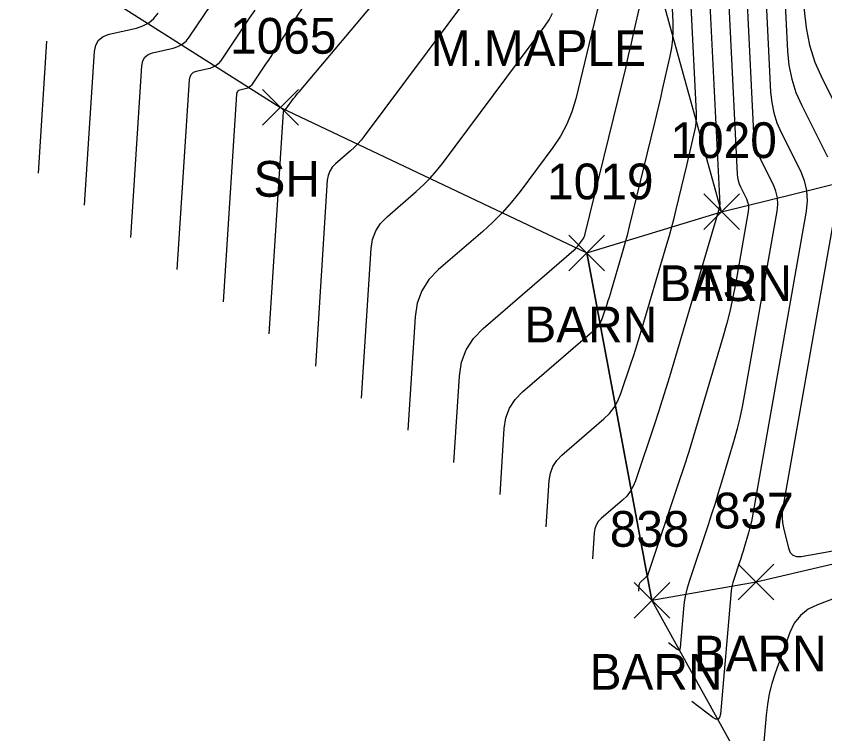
# Model space of a CAD drawing. Extents: x 1650836 to 1652450, y 332578 to 333908.
# Drawn here: x 1651941.6 to 1651986.84, y 332758.18 to 332798.32 of the extents above; entities that cross this region are included whole.
import ezdxf

# ---------------------------------------------------------------- set-up
doc = ezdxf.new("R2010")
doc.units = 0
for name, color, linetype in [('L_A', 7, 'Continuous'), ('L_C', 7, 'Continuous'), ('L_I', 7, 'Continuous'), ('L_TIC', 7, 'Continuous'), ('LBC', 7, 'Continuous'), ('LELB', 7, 'Continuous'), ('LSOGCMA', 7, 'Continuous'), ('LSOGCMI', 7, 'Continuous'), ('LSOGP', 7, 'Continuous')]:
    doc.layers.add(name, color=color, linetype=linetype)

msp = doc.modelspace()

# ---------------------------------------------------------------- linework, layer by layer
at = {"layer": 'L_TIC'}
for points in [[(1651955.389, 332792.224), (1651957.389, 332794.224)], [(1651957.389, 332792.224), (1651955.389, 332794.224)], [(1651980.067, 332786.388), (1651982.067, 332788.388)], [(1651982.067, 332786.388), (1651980.067, 332788.388)], [(1651980.067, 332786.388), (1651982.067, 332788.388)], [(1651982.067, 332786.388), (1651980.067, 332788.388)], [(1651972.519, 332784.08), (1651974.519, 332786.08)], [(1651974.519, 332784.08), (1651972.519, 332786.08)], [(1651981.996, 332765.671), (1651983.996, 332767.671)], [(1651983.996, 332765.671), (1651981.996, 332767.671)], [(1651976.172, 332764.646), (1651978.172, 332766.646)], [(1651978.172, 332764.646), (1651976.172, 332766.646)]]:
    msp.add_lwpolyline(points, dxfattribs=at)
at = {"layer": 'LBC'}
msp.add_lwpolyline([(1652023.947, 332796.746), (1652025.548, 332786.282), (1652005.235, 332781.934), (1652007.106, 332772.495), (1652006.921, 332772.261), (1651982.996, 332766.671), (1651977.172, 332765.646), (1651973.519, 332785.08), (1651981.067, 332787.388), (1651992.104, 332790.093), (1652005.024, 332792.832)], dxfattribs=at)
at = {"layer": 'LELB'}
msp.add_lwpolyline([(1651981.067, 332787.388), (1651974.596, 332810.786), (1651972.976, 332830.46), (1651956.891, 332837.411), (1651913.583, 332855.638), (1651885.106, 332867.214), (1651834.429, 332888.588)], dxfattribs=at)
at = {"layer": 'LSOGCMA'}
msp.add_lwpolyline([(1651966.091, 332773.361), (1651966.4, 332778.193), (1651966.521, 332778.963), (1651966.783, 332779.664), (1651967.184, 332780.296), (1651967.725, 332780.857), (1651972.798, 332785.23), (1651972.868, 332785.294), (1651972.935, 332785.362), (1651972.997, 332785.433), (1651973.056, 332785.507), (1651973.284, 332785.813), (1651973.337, 332785.891), (1651973.381, 332785.974), (1651973.416, 332786.06), (1651973.443, 332786.151), (1651975.535, 332794.734), (1651975.702, 332795.424), (1651975.866, 332796.115), (1651976.026, 332796.806), (1651976.184, 332797.498), (1651976.809, 332800.267)], dxfattribs=at)
at = {"layer": 'LSOGCMI'}
for points in [[(1651986.916, 332818.732), (1651986.557, 332816.279), (1651986.495, 332815.844), (1651986.434, 332815.409), (1651986.375, 332814.974), (1651986.319, 332814.538), (1651985.584, 332808.772), (1651985.468, 332807.665), (1651985.4, 332806.556), (1651985.382, 332805.444), (1651985.412, 332804.332), (1651985.691, 332798.664), (1651985.791, 332797.669), (1651985.991, 332796.701), (1651986.291, 332795.759), (1651986.691, 332794.844), (1651988.494, 332791.234)], [(1651968.674, 332771.563), (1651968.911, 332775.268), (1651969.004, 332775.859), (1651969.204, 332776.397), (1651969.512, 332776.881), (1651969.927, 332777.312), (1651973.966, 332780.794), (1651974.109, 332780.934), (1651974.23, 332781.09), (1651974.328, 332781.261), (1651974.404, 332781.446), (1651974.663, 332782.22), (1651974.727, 332782.413), (1651974.789, 332782.608), (1651974.85, 332782.802), (1651974.908, 332782.998), (1651975.491, 332784.967), (1651975.605, 332785.361), (1651975.714, 332785.757), (1651975.818, 332786.154), (1651975.918, 332786.551), (1651977.331, 332792.35), (1651977.443, 332792.816), (1651977.554, 332793.282), (1651977.662, 332793.749), (1651977.769, 332794.216), (1651978.191, 332796.087), (1651978.281, 332796.556), (1651978.338, 332797.028), (1651978.363, 332797.502), (1651978.355, 332797.98), (1651977.82, 332808.862)], [(1651971.256, 332769.765), (1651971.421, 332772.344), (1651971.486, 332772.755), (1651971.626, 332773.13), (1651971.84, 332773.467), (1651972.129, 332773.766), (1651974.487, 332775.799), (1651974.797, 332776.103), (1651975.058, 332776.44), (1651975.271, 332776.81), (1651975.436, 332777.212), (1651975.996, 332778.887), (1651976.134, 332779.306), (1651976.269, 332779.726), (1651976.4, 332780.148), (1651976.527, 332780.571), (1651978.006, 332785.575), (1651978.146, 332786.058), (1651978.28, 332786.542), (1651978.408, 332787.029), (1651978.53, 332787.517), (1651979.126, 332789.965), (1651979.185, 332790.207), (1651979.242, 332790.449), (1651979.299, 332790.692), (1651979.354, 332790.935), (1651979.573, 332791.906), (1651979.62, 332792.15), (1651979.649, 332792.395), (1651979.662, 332792.642), (1651979.659, 332792.89), (1651978.905, 332808.215)], [(1651979.989, 332807.568), (1651980.962, 332787.799), (1651980.962, 332787.781), (1651980.961, 332787.762), (1651980.959, 332787.744), (1651980.955, 332787.726), (1651980.939, 332787.653), (1651980.935, 332787.635), (1651980.931, 332787.617), (1651980.926, 332787.599), (1651980.922, 332787.581), (1651980.877, 332787.397), (1651980.868, 332787.361), (1651980.859, 332787.325), (1651980.849, 332787.288), (1651980.838, 332787.252), (1651978.145, 332778.144), (1651977.95, 332777.494), (1651977.749, 332776.845), (1651977.542, 332776.199), (1651977.329, 332775.554), (1651976.253, 332772.339), (1651976.126, 332772.028), (1651975.961, 332771.741), (1651975.758, 332771.48), (1651975.518, 332771.244), (1651974.331, 332770.221), (1651974.168, 332770.052), (1651974.047, 332769.862), (1651973.969, 332769.651), (1651973.932, 332769.42), (1651973.839, 332767.966)], [(1651955.759, 332780.554), (1651956.554, 332792.968), (1651956.556, 332792.984), (1651956.562, 332793), (1651956.571, 332793.013), (1651956.582, 332793.026), (1651956.636, 332793.072), (1651956.648, 332793.083), (1651956.661, 332793.096), (1651956.672, 332793.109), (1651956.683, 332793.123), (1651957.123, 332793.713), (1651957.201, 332793.815), (1651957.28, 332793.917), (1651957.361, 332794.017), (1651957.443, 332794.116), (1651968.415, 332807.145)], [(1651981.074, 332806.921), (1651981.931, 332789.495), (1651981.95, 332789.309), (1651981.987, 332789.128), (1651982.043, 332788.952), (1651982.118, 332788.781), (1651982.455, 332788.106), (1651982.524, 332787.936), (1651982.565, 332787.761), (1651982.576, 332787.581), (1651982.558, 332787.398), (1651981.842, 332783.341), (1651981.701, 332782.605), (1651981.54, 332781.874), (1651981.358, 332781.148), (1651981.156, 332780.427), (1651979.764, 332775.717), (1651979.5, 332774.839), (1651979.228, 332773.964), (1651978.949, 332773.091), (1651978.662, 332772.221), (1651976.965, 332767.152), (1651976.937, 332767.082), (1651976.899, 332767.018), (1651976.854, 332766.959), (1651976.8, 332766.906), (1651976.533, 332766.675), (1651976.496, 332766.637), (1651976.469, 332766.595), (1651976.451, 332766.547), (1651976.443, 332766.495), (1651976.422, 332766.168)], [(1651978.102, 332763.298), (1651978.582, 332762.928), (1651978.654, 332762.886), (1651978.707, 332762.885), (1651978.742, 332762.925), (1651978.76, 332763.006), (1651978.95, 332765.179), (1651978.996, 332765.573), (1651979.065, 332765.962), (1651979.156, 332766.346), (1651979.271, 332766.725), (1651980.332, 332769.895), (1651980.527, 332770.487), (1651980.717, 332771.08), (1651980.902, 332771.675), (1651981.081, 332772.271), (1651981.787, 332774.661), (1651981.955, 332775.26), (1651982.106, 332775.863), (1651982.24, 332776.471), (1651982.357, 332777.082), (1651984.179, 332787.409), (1651984.217, 332787.792), (1651984.194, 332788.166), (1651984.11, 332788.532), (1651983.964, 332788.888), (1651983.261, 332790.297), (1651983.105, 332790.654), (1651982.988, 332791.021), (1651982.91, 332791.399), (1651982.871, 332791.787), (1651982.158, 332806.273)], [(1651983.243, 332805.626), (1651983.811, 332794.079), (1651983.87, 332793.489), (1651983.989, 332792.915), (1651984.167, 332792.356), (1651984.405, 332791.812), (1651985.474, 332789.67), (1651985.695, 332789.128), (1651985.823, 332788.572), (1651985.858, 332788.003), (1651985.801, 332787.42), (1651982.775, 332770.27), (1651982.734, 332770.059), (1651982.688, 332769.849), (1651982.636, 332769.64), (1651982.578, 332769.433), (1651982.334, 332768.607), (1651982.272, 332768.401), (1651982.208, 332768.195), (1651982.142, 332767.99), (1651982.075, 332767.786), (1651981.768, 332766.87), (1651981.701, 332766.648), (1651981.648, 332766.424), (1651981.607, 332766.196), (1651981.58, 332765.966), (1651980.998, 332759.285), (1651980.955, 332759.091), (1651980.87, 332758.995), (1651980.741, 332758.997), (1651980.57, 332759.097), (1651979.411, 332759.99)], [(1651984.328, 332804.979), (1651984.751, 332796.371), (1651984.83, 332795.579), (1651984.99, 332794.808), (1651985.229, 332794.057), (1651985.548, 332793.328), (1651986.984, 332790.452)], [(1651970.429, 332804.157), (1651961.066, 332791.607), (1651960.893, 332791.388), (1651960.71, 332791.18), (1651960.515, 332790.983), (1651960.31, 332790.795), (1651959.465, 332790.067), (1651959.278, 332789.873), (1651959.139, 332789.655), (1651959.049, 332789.413), (1651959.007, 332789.146), (1651958.342, 332778.756)], [(1651948.011, 332785.948), (1651948.625, 332795.553), (1651948.677, 332795.818), (1651948.796, 332796.026), (1651948.982, 332796.176), (1651949.235, 332796.271), (1651950.379, 332796.533), (1651950.65, 332796.621), (1651950.891, 332796.753), (1651951.101, 332796.93), (1651951.28, 332797.151), (1651953.742, 332800.795)], [(1651959.011, 332800.967), (1651956.13, 332796.514), (1651955.986, 332796.292), (1651955.84, 332796.072), (1651955.694, 332795.852), (1651955.547, 332795.632), (1651954.764, 332794.473), (1651954.707, 332794.403), (1651954.64, 332794.347), (1651954.564, 332794.305), (1651954.477, 332794.277), (1651954.113, 332794.193), (1651954.033, 332794.163), (1651953.974, 332794.115), (1651953.936, 332794.049), (1651953.919, 332793.965), (1651953.176, 332782.352)], [(1651974.178, 332798.947), (1651973.978, 332798.104), (1651973.775, 332797.262), (1651972.907, 332793.702), (1651972.691, 332792.973), (1651972.405, 332792.276), (1651972.05, 332791.612), (1651971.626, 332790.98), (1651969.79, 332788.52), (1651969.316, 332787.919), (1651968.811, 332787.347), (1651968.276, 332786.803), (1651967.71, 332786.287), (1651965.23, 332784.15), (1651964.693, 332783.592), (1651964.294, 332782.965), (1651964.034, 332782.269), (1651963.914, 332781.504), (1651963.508, 332775.159)], [(1651945.428, 332787.747), (1651945.978, 332796.347), (1651946.048, 332796.702), (1651946.208, 332796.981), (1651946.457, 332797.183), (1651946.796, 332797.309), (1651948.33, 332797.661), (1651948.694, 332797.779), (1651949.016, 332797.956), (1651949.298, 332798.193), (1651949.538, 332798.49)], [(1651954.95, 332798.668), (1651954.644, 332798.213), (1651953.022, 332795.812), (1651952.904, 332795.666), (1651952.765, 332795.55), (1651952.607, 332795.463), (1651952.428, 332795.405), (1651951.674, 332795.232), (1651951.508, 332795.17), (1651951.385, 332795.07), (1651951.307, 332794.934), (1651951.272, 332794.759), (1651950.594, 332784.15)], [(1651960.925, 332776.957), (1651961.46, 332785.325), (1651961.542, 332785.841), (1651961.717, 332786.31), (1651961.985, 332786.732), (1651962.348, 332787.108), (1651963.984, 332788.519), (1651964.382, 332788.882), (1651964.759, 332789.265), (1651965.114, 332789.668), (1651965.448, 332790.09), (1651971.178, 332797.771), (1651971.414, 332798.123), (1651971.612, 332798.492)], [(1651942.845, 332789.545), (1651943.317, 332796.922)], [(1651987.423, 332787.431), (1651984.495, 332770.84), (1651984.459, 332770.554), (1651984.453, 332770.269), (1651984.477, 332769.985), (1651984.53, 332769.701), (1651984.802, 332768.57), (1651984.897, 332768.329), (1651985.047, 332768.171), (1651985.251, 332768.097), (1651985.511, 332768.106), (1651996.778, 332770.111)], [(1651996.975, 332769.395), (1651986.424, 332765.406), (1651985.904, 332765.148), (1651985.475, 332764.802), (1651985.135, 332764.367), (1651984.886, 332763.843), (1651984.069, 332761.571), (1651983.884, 332760.999), (1651983.736, 332760.419), (1651983.627, 332759.83), (1651983.556, 332759.233), (1651983.236, 332755.564), (1651983.168, 332755.257), (1651983.033, 332755.105), (1651982.829, 332755.108), (1651982.557, 332755.266), (1651980.721, 332756.682)]]:
    msp.add_lwpolyline(points, dxfattribs=at)
at = {"layer": 'LSOGP'}
msp.add_lwpolyline([(1651814.272, 332938.956), (1651818.842, 332935.985), (1651823.411, 332933.014), (1651827.981, 332930.043), (1651832.551, 332927.072), (1651837.12, 332924.1), (1651841.69, 332921.129), (1651846.26, 332918.158), (1651844.759, 332915.941), (1651847.527, 332911.35), (1651845.231, 332908.813), (1651834.429, 332888.588), (1651826.845, 332873.564), (1651850.897, 332857.776), (1651861.906, 332843.614), (1651887.79, 332823.882), (1651895.345, 332817.735), (1651915.287, 332808.731), (1651939.148, 332804.133), (1651956.389, 332793.224), (1651973.519, 332785.08), (1651977.172, 332765.646), (1651984.523, 332752.343)], dxfattribs=at)

# ---------------------------------------------------------------- texts
at = {"layer": 'L_A'}
for s, p in [('SH', (1651954.877, 332788.224)), ('BARN', (1651977.579, 332782.388)), ('TS', (1651979.477, 332782.388)), ('BARN', (1651970.031, 332780.08)), ('BARN', (1651979.507, 332761.671)), ('BARN', (1651973.684, 332760.646))]:
    msp.add_text(s, height=2, dxfattribs=at).set_placement(p)
at = {"layer": 'L_C'}
msp.add_text('M.MAPLE', height=2, dxfattribs=at).set_placement((1651964.795, 332795.534))
at = {"layer": 'L_I'}
for s, p in [('1065', (1651953.57, 332796.224)), ('1020', (1651978.209, 332790.388)), ('1020', (1651978.209, 332790.388)), ('1019', (1651971.307, 332788.08)), ('837', (1651980.633, 332769.671)), ('838', (1651974.81, 332768.646))]:
    msp.add_text(s, height=2, dxfattribs=at).set_placement(p)

doc.saveas('drawing.dxf')
